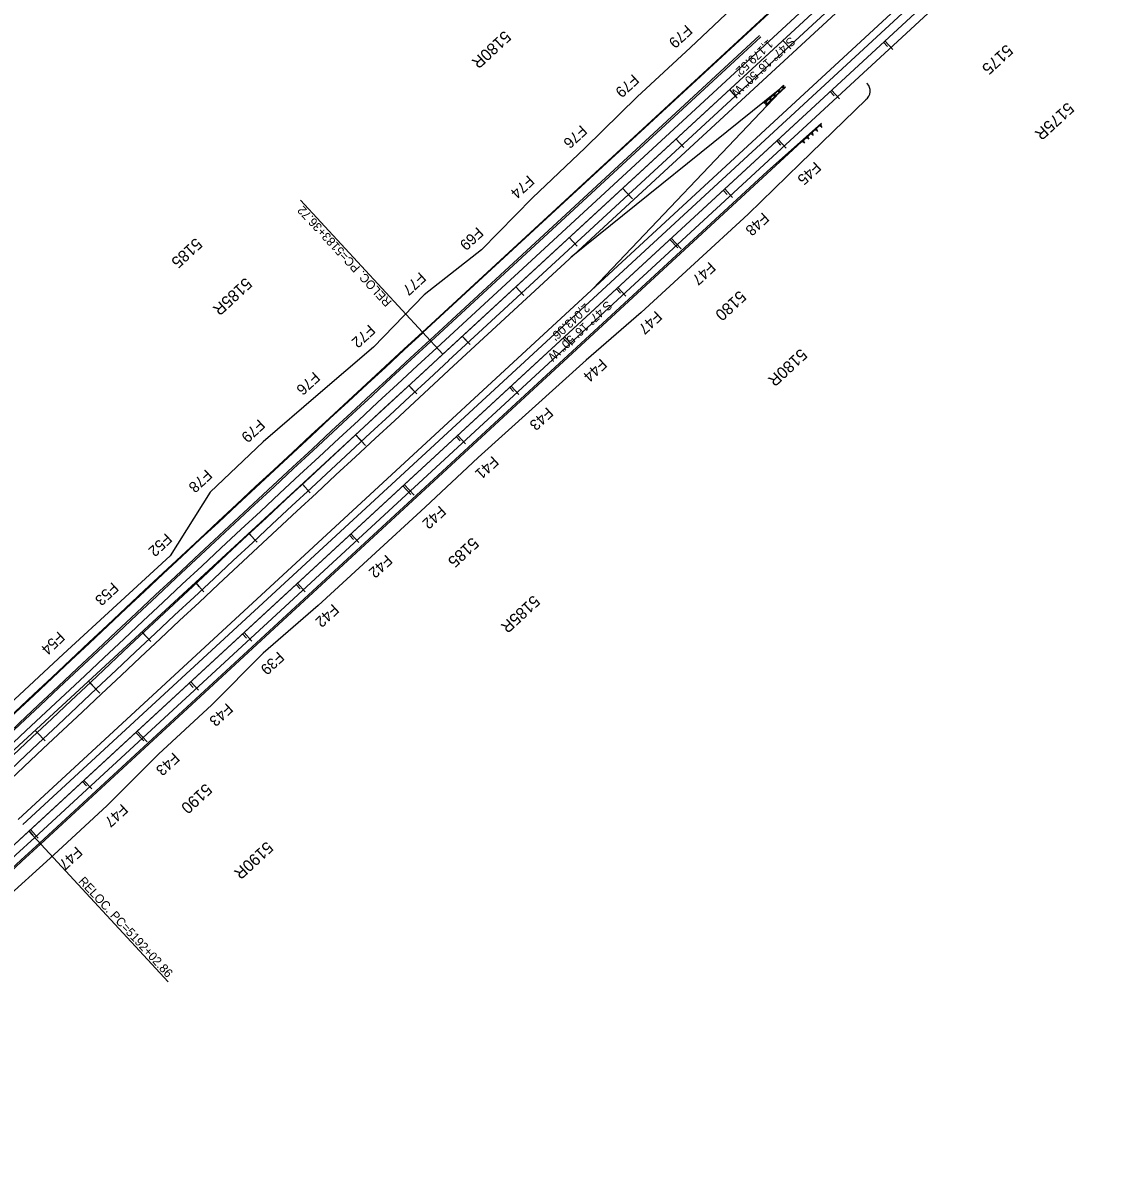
# Model space of a CAD drawing. Extents: x 2160877 to 2175861, y 601747 to 617724.
# Drawn here: x 2170763 to 2172272, y 611849 to 613431 of the extents above; entities that cross this region are included whole.
import ezdxf

# ---------------------------------------------------------------- set-up
doc = ezdxf.new("R2010")
doc.units = 0
for name, color, linetype in [('RD_HC_Cl', 7, 'Continuous'), ('RD_HC_CL_Rel', 7, 'Continuous'), ('RD_HC_Data_Rel', 7, 'Continuous'), ('RD_HC_Data_Tic', 7, 'Continuous'), ('RD_HC_Data_Tic_Rel', 7, 'Continuous'), ('RD_HC_TX_Rel_Sta50', 7, 'Continuous'), ('RD_HC_TX_Rel_StaOther', 7, 'Continuous'), ('RD_HC_TX_StaOther', 7, 'Continuous'), ('RD_PD_CstnLmt', 7, 'Continuous'), ('RD_PD_CstnLmt_TX', 7, 'Continuous'), ('RD_PD_Final_LnLine', 7, 'Continuous'), ('RD_PD_Final_TrvlWay', 7, 'Continuous'), ('RD_PD_GR', 7, 'Continuous'), ('RD_PD_MedBWall', 7, 'Continuous')]:
    doc.layers.add(name, color=color, linetype=linetype)

msp = doc.modelspace()

# ---------------------------------------------------------------- linework, layer by layer
at = {"layer": 'RD_HC_Cl'}
for p, q in [((2172207.3, 613775.1), (2163672.2, 605893.8)), ((2172272.5, 613704.6), (2163737.4, 605823.3))]:
    msp.add_line(p, q, dxfattribs=at)
at = {"layer": 'RD_HC_CL_Rel'}
for p, q in [((2172207.3, 613775.1), (2171340.7, 612974.9)), ((2172272.5, 613704.6), (2170771.4, 612318.6))]:
    msp.add_line(p, q, dxfattribs=at)
for centre, radius in [((2222221.5, 557873.6), 75000), ((2219616.9, 559421.3), 72000)]:
    msp.add_arc(centre, radius, 132.719474, 134.517591, dxfattribs=at)
at = {"layer": 'RD_HC_Data_Rel'}
for p, q in [((2171340.7, 612974.9), (2171145.2, 613186.7)), ((2170771.4, 612318.6), (2170963.2, 612110.9))]:
    msp.add_line(p, q, dxfattribs=at)
at = {"layer": 'RD_HC_Data_Tic'}
for p, q in [((2171808.5, 613406.9), (2171814, 613401)), ((2171947.1, 613404.2), (2171952.6, 613398.3)), ((2171735.1, 613339.1), (2171740.5, 613333.2)), ((2171873.7, 613336.4), (2171879.1, 613330.5)), ((2171661.6, 613271.2), (2171667, 613265.3)), ((2171800.2, 613268.5), (2171805.6, 613262.7)), ((2171588.1, 613203.4), (2171599, 613191.6)), ((2171726.7, 613200.7), (2171732.2, 613194.8)), ((2171514.7, 613135.5), (2171520.1, 613129.7)), ((2171653.3, 613132.8), (2171664.1, 613121.1)), ((2171441.2, 613067.7), (2171446.6, 613061.8)), ((2171579.8, 613065), (2171585.2, 613059.1)), ((2171367.7, 612999.9), (2171373.2, 612994)), ((2171506.3, 612997.2), (2171511.8, 612991.3)), ((2171294.3, 612932), (2171299.7, 612926.1)), ((2171432.9, 612929.3), (2171438.3, 612923.4)), ((2171220.8, 612864.2), (2171231.6, 612852.4)), ((2171359.4, 612861.5), (2171364.8, 612855.6)), ((2171147.3, 612796.3), (2171152.7, 612790.5)), ((2171285.9, 612793.6), (2171296.8, 612781.9)), ((2171073.9, 612728.5), (2171079.3, 612722.6)), ((2171212.4, 612725.8), (2171217.9, 612719.9)), ((2171000.4, 612660.7), (2171005.8, 612654.8)), ((2171139, 612658), (2171144.4, 612652.1)), ((2170926.9, 612592.8), (2170932.3, 612586.9)), ((2171065.5, 612590.1), (2171070.9, 612584.2)), ((2170853.4, 612525), (2170864.3, 612513.2)), ((2170992, 612522.3), (2170997.5, 612516.4)), ((2170780, 612457.1), (2170785.4, 612451.3)), ((2170918.6, 612454.4), (2170929.4, 612442.7)), ((2170845.1, 612386.6), (2170850.5, 612380.7)), ((2170771.6, 612318.8), (2170777.1, 612312.9))]:
    msp.add_line(p, q, dxfattribs=at)
at = {"layer": 'RD_HC_Data_Tic_Rel'}
for p, q in [((2171808.5, 613406.9), (2171819.4, 613395.1)), ((2171949, 613406), (2171959.9, 613394.2)), ((2171735.1, 613339.1), (2171745.9, 613327.3)), ((2171875.6, 613338.1), (2171886.4, 613326.4)), ((2171661.6, 613271.2), (2171672.5, 613259.5)), ((2171802.1, 613270.3), (2171813, 613258.5)), ((2171588.1, 613203.4), (2171601.7, 613188.7)), ((2171728.6, 613202.5), (2171739.5, 613190.7)), ((2171514.7, 613135.5), (2171525.5, 613123.8)), ((2171655.2, 613134.6), (2171668.7, 613119.9)), ((2171441.2, 613067.7), (2171452.1, 613055.9)), ((2171581.7, 613066.8), (2171592.6, 613055)), ((2171367.7, 612999.9), (2171378.6, 612988.1)), ((2171508.2, 612998.9), (2171519.1, 612987.2)), ((2171294.3, 612932), (2171305.1, 612920.2)), ((2171434.8, 612931.1), (2171445.6, 612919.3)), ((2171220.9, 612864), (2171234.5, 612849.4)), ((2171361.3, 612863.2), (2171372.2, 612851.5)), ((2171147.6, 612796), (2171158.5, 612784.3)), ((2171287.8, 612795.4), (2171301.4, 612780.7)), ((2171074.5, 612727.8), (2171085.4, 612716.1)), ((2171214.4, 612727.6), (2171225.2, 612715.8)), ((2171001.4, 612659.6), (2171012.3, 612647.9)), ((2171140.9, 612659.7), (2171151.7, 612648)), ((2170928.4, 612591.3), (2170939.3, 612579.6)), ((2171067.4, 612591.9), (2171078.3, 612580.1)), ((2170855.4, 612522.8), (2170869.1, 612508.2)), ((2170994, 612524), (2171004.8, 612512.3)), ((2170782.6, 612454.3), (2170793.6, 612442.6)), ((2170920.5, 612456.2), (2170934.1, 612441.5)), ((2170847, 612388.4), (2170857.9, 612376.6)), ((2170773.5, 612320.5), (2170784.4, 612308.8))]:
    msp.add_line(p, q, dxfattribs=at)
at = {"layer": 'RD_PD_CstnLmt'}
for p, q in [((2171754.2, 613465.7), (2171681.6, 613397)), ((2171681.6, 613397), (2171608.1, 613329.1)), ((2171924.2, 613348.1), (2171924.8, 613347.4)), ((2171608.1, 613329.1), (2171536.7, 613259)), ((2171922.9, 613325.2), (2171832.4, 613237.5)), ((2171536.7, 613259), (2171464.3, 613190.1)), ((2171832.4, 613237.5), (2171760.9, 613167.5)), ((2171464.3, 613190.1), (2171394.1, 613118.7)), ((2171760.9, 613167.5), (2171687.3, 613099.8)), ((2171394.1, 613118.7), (2171315.2, 613056.8)), ((2171687.3, 613099.8), (2171613.7, 613032.1)), ((2171315.2, 613056.8), (2171245.5, 612984.7)), ((2171613.7, 613032.1), (2171538.1, 612966.6)), ((2171245.5, 612984.7), (2171169.4, 612919.6)), ((2171538.1, 612966.6), (2171463.8, 612899.6)), ((2171169.4, 612919.6), (2171093.5, 612854.2)), ((2171463.8, 612899.6), (2171389.4, 612832.8)), ((2171093.5, 612854.2), (2171021, 612785.2)), ((2171389.4, 612832.8), (2171316.6, 612764.2)), ((2171021, 612785.2), (2170966, 612697.4)), ((2171316.6, 612764.2), (2171242.9, 612696.6)), ((2170966, 612697.4), (2170892.2, 612629.8)), ((2171242.9, 612696.6), (2171169.4, 612628.9)), ((2170892.2, 612629.8), (2170818.5, 612562.2)), ((2171169.4, 612628.9), (2171093.9, 612563.2)), ((2170818.5, 612562.2), (2170745.3, 612493.8)), ((2171093.9, 612563.2), (2171023.3, 612492.3)), ((2171023.3, 612492.3), (2170949.9, 612424.4)), ((2170949.9, 612424.4), (2170879, 612353.7)), ((2170879, 612353.7), (2170805.7, 612285.7)), ((2170805.7, 612285.7), (2170731.3, 612218.9))]:
    msp.add_line(p, q, dxfattribs=at)
msp.add_arc((2171913.8, 613337.2), 15, 307.2254, 42.7195, dxfattribs=at)
at = {"layer": 'RD_PD_Final_LnLine'}
for p, q in [((2172199.2, 613784), (2171332.6, 612983.8)), ((2172215.5, 613766.3), (2171348.9, 612966.1)), ((2172264.3, 613713.4), (2170763.3, 612327.4)), ((2172224.1, 613643.7), (2170779.6, 612309.8)), ((2171802, 613337.9), (2171517.6, 613108.3)), ((2171804.3, 613335.4), (2171547.4, 613065))]:
    msp.add_line(p, q, dxfattribs=at)
for centre, radius in [((2222221.5, 557873.6), 75012), ((2222221.5, 557873.6), 74988), ((2219616.9, 559421.3), 71988)]:
    msp.add_arc(centre, radius, 132.719474, 134.517591, dxfattribs=at)
at = {"layer": 'RD_PD_Final_TrvlWay'}
for p, q in [((2172222.2, 613759), (2171355.7, 612958.8)), ((2172257.5, 613720.8), (2170756.5, 612334.7)), ((2171776.7, 613413.4), (2171322.9, 612994.3)), ((2171778.3, 613411.6), (2171324.5, 612992.6)), ((2171787.2, 613226.6), (2171862, 613293)), ((2171787.2, 613226.6), (2170786.4, 612302.4))]:
    msp.add_line(p, q, dxfattribs=at)
for centre, radius in [((2222220.1, 557875.1), 75024.3), ((2222220.1, 557875.1), 75022), ((2222221.5, 557873.6), 74978), ((2219616.9, 559421.3), 71978)]:
    msp.add_arc(centre, radius, 132.719474, 134.517591, dxfattribs=at)
at = {"layer": 'RD_PD_GR'}
for p, q in [((2171809.9, 613345.3), (2171782.7, 613320.2)), ((2171783, 613319.8), (2171810.2, 613344.9)), ((2171784.9, 613317.9), (2171812, 613343)), ((2171812.4, 613342.6), (2171785.2, 613317.5)), ((2171801.4, 613337.6), (2171802.6, 613338.7)), ((2171801.8, 613337.1), (2171803, 613338.3)), ((2171803.1, 613335.7), (2171801.8, 613337.1)), ((2171802.9, 613337.2), (2171802, 613338.1)), ((2171803.5, 613337.8), (2171802.2, 613336.6)), ((2171802.2, 613336.6), (2171803.6, 613335.2)), ((2171803, 613338.3), (2171804.4, 613336.8)), ((2171804.4, 613336.8), (2171803.1, 613335.7)), ((2171804.9, 613336.4), (2171803.5, 613337.8)), ((2171803.6, 613335.2), (2171804.9, 613336.4)), ((2171803.8, 613336.2), (2171804.6, 613335.3)), ((2171807.2, 613343), (2171808.5, 613344.2)), ((2171807.6, 613342.6), (2171808.9, 613343.7)), ((2171809, 613341.1), (2171807.6, 613342.6)), ((2171808.7, 613342.7), (2171807.9, 613343.6)), ((2171809.4, 613343.2), (2171808.1, 613342.1)), ((2171808.1, 613342.1), (2171809.4, 613340.6)), ((2171808.9, 613343.7), (2171810.3, 613342.3)), ((2171810.3, 613342.3), (2171809, 613341.1)), ((2171810.7, 613341.8), (2171809.4, 613343.2)), ((2171809.4, 613340.6), (2171810.7, 613341.8)), ((2171809.6, 613341.7), (2171810.5, 613340.8)), ((2171809.8, 613340.2), (2171811.1, 613341.3)), ((2171810.2, 613344.9), (2171809.9, 613345.3)), ((2171812, 613343), (2171812.4, 613342.6)), ((2171783.7, 613321.3), (2171785, 613322.5)), ((2171784.1, 613320.8), (2171785.4, 613322)), ((2171785.5, 613319.4), (2171784.1, 613320.8)), ((2171785.2, 613320.9), (2171784.4, 613321.9)), ((2171785.9, 613321.5), (2171784.6, 613320.4)), ((2171785.4, 613322), (2171786.8, 613320.6)), ((2171786.8, 613320.6), (2171785.5, 613319.4)), ((2171787.2, 613320.1), (2171785.9, 613321.5)), ((2171787.7, 613324.1), (2171787.4, 613324.5)), ((2171789.5, 613322.2), (2171789.9, 613321.8)), ((2171789.6, 613326.7), (2171790.9, 613327.9)), ((2171790, 613326.3), (2171791.3, 613327.5)), ((2171791.4, 613324.8), (2171790, 613326.3)), ((2171791.1, 613326.4), (2171790.3, 613327.3)), ((2171791.7, 613327), (2171790.5, 613325.8)), ((2171790.5, 613325.8), (2171791.8, 613324.3)), ((2171791.3, 613327.5), (2171792.6, 613326)), ((2171792.6, 613326), (2171791.4, 613324.8)), ((2171793.1, 613325.5), (2171791.7, 613327)), ((2171791.8, 613324.3), (2171793.1, 613325.5)), ((2171792, 613325.4), (2171792.9, 613324.5)), ((2171792.2, 613323.9), (2171793.5, 613325.1)), ((2171795.5, 613332.1), (2171796.8, 613333.3)), ((2171795.9, 613331.7), (2171797.2, 613332.9)), ((2171797.2, 613330.2), (2171795.9, 613331.7)), ((2171797, 613331.8), (2171796.1, 613332.7)), ((2171797.6, 613332.4), (2171796.3, 613331.2)), ((2171796.3, 613331.2), (2171797.7, 613329.7)), ((2171797.2, 613332.9), (2171798.5, 613331.4)), ((2171798.5, 613331.4), (2171797.2, 613330.2)), ((2171799, 613330.9), (2171797.6, 613332.4)), ((2171797.7, 613329.7), (2171799, 613330.9)), ((2171797.9, 613330.8), (2171798.7, 613329.9)), ((2171798.1, 613329.3), (2171799.4, 613330.5)), ((2171804, 613334.7), (2171805.3, 613335.9)), ((2171782.7, 613320.2), (2171783, 613319.8)), ((2171784.6, 613320.4), (2171785.9, 613318.9)), ((2171785.2, 613317.5), (2171784.9, 613317.9)), ((2171785.9, 613318.9), (2171787.2, 613320.1)), ((2171786.1, 613320), (2171787, 613319)), ((2171786.3, 613318.5), (2171787.6, 613319.6)), ((2171861.2, 613292.3), (2171834.1, 613267.2)), ((2171834.4, 613266.9), (2171861.6, 613292)), ((2171859, 613289.6), (2171860.3, 613290.8)), ((2171860.3, 613288.1), (2171859, 613289.6)), ((2171860.3, 613290.8), (2171861.6, 613289.3)), ((2171861.6, 613289.3), (2171860.3, 613288.1)), ((2171861.6, 613292), (2171861.2, 613292.3)), ((2171841.4, 613273.3), (2171842.6, 613274.5)), ((2171842.7, 613271.8), (2171841.4, 613273.3)), ((2171842.6, 613274.5), (2171844, 613273)), ((2171844, 613273), (2171842.7, 613271.8)), ((2171847.2, 613278.7), (2171848.5, 613279.9)), ((2171848.6, 613277.3), (2171847.2, 613278.7)), ((2171848.5, 613279.9), (2171849.9, 613278.4)), ((2171849.9, 613278.4), (2171848.6, 613277.3)), ((2171849.2, 613277.8), (2171850.1, 613276.9)), ((2171849.4, 613276.3), (2171850.7, 613277.5)), ((2171853.1, 613284.2), (2171854.4, 613285.3)), ((2171854.5, 613282.7), (2171853.1, 613284.2)), ((2171854.4, 613285.3), (2171855.7, 613283.9)), ((2171855.7, 613283.9), (2171854.5, 613282.7)), ((2171855.1, 613283.3), (2171856, 613282.4)), ((2171855.3, 613281.8), (2171856.6, 613283)), ((2171861, 613288.7), (2171861.8, 613287.8)), ((2171861.2, 613287.2), (2171862.5, 613288.4)), ((2170787.7, 612300.9), (2171834.1, 613267.2)), ((2171834.1, 613267.2), (2171834.4, 613266.9)), ((2171835.5, 613267.9), (2171836.8, 613269.1)), ((2171836.8, 613266.4), (2171835.5, 613267.9)), ((2171836.8, 613269.1), (2171838.1, 613267.6)), ((2171838.1, 613267.6), (2171836.8, 613266.4)), ((2171837.5, 613267), (2171838.3, 613266.1)), ((2171837.7, 613265.5), (2171839, 613266.7)), ((2171839.1, 613271.2), (2171838.7, 613271.5)), ((2171843.4, 613272.4), (2171844.2, 613271.5)), ((2171843.6, 613270.9), (2171844.8, 613272.1))]:
    msp.add_line(p, q, dxfattribs=at)
msp.add_arc((2219616.9, 559421.3), 71976, 132.719474, 134.517591, dxfattribs=at)
at = {"layer": 'RD_PD_MedBWall'}
for p, q in [((2172075.1, 613709.3), (2171312.7, 613005.3)), ((2172075.8, 613708.6), (2171313.4, 613004.6))]:
    msp.add_line(p, q, dxfattribs=at)
for radius, end in [(75039.3, 134.421287), (75038.3, 134.421298)]:
    msp.add_arc((2222220.1, 557875.1), radius, 132.719474, end, dxfattribs=at)

# ---------------------------------------------------------------- texts
at = {"layer": 'RD_HC_Data_Rel'}
for s, rotation, p in [('RELOC. PC=5183+36.72', 132.7195, (2171271.4, 613047.1)), ('RELOC. PC=5192+02.86', 312.7195, (2170838.9, 612248.9))]:
    msp.add_text(s, height=12, rotation=rotation, dxfattribs=at).set_placement(p)
at = {"layer": 'RD_HC_TX_Rel_Sta50'}
for s, rotation, p in [('5180R', 222.7195, (2171425.6, 613421.1)), ('5175R', 222.7195, (2172200.2, 613322.6)), ('5185R', 222.8442, (2171069.3, 613081.3)), ('5180R', 222.7195, (2171833.1, 612983.6)), ('5185R', 222.7195, (2171465.5, 612644.2)), ('5190R', 222.7195, (2171098.4, 612305.2))]:
    msp.add_text(s, height=16, rotation=rotation, dxfattribs=at).set_placement(p)
at = {"layer": 'RD_HC_TX_Rel_StaOther'}
for s, p in [('S 47%%d 16\' 50" W', (2171819.1, 613412.6)), ("1,179.52'", (2171788.7, 613409)), ('S 47%%d 16\' 50" W', (2171567, 613049.2)), ("2,043.06'", (2171536.6, 613045.6))]:
    msp.add_text(s, height=12, rotation=222.7195, dxfattribs=at).set_placement(p)
at = {"layer": 'RD_HC_TX_StaOther'}
for s, p in [('5175', (2172116.1, 613402.3)), ('5185', (2171000.9, 613136)), ('5180', (2171749.1, 613063.5)), ('5185', (2171381.4, 612723.9)), ('5190', (2171014.4, 612385))]:
    msp.add_text(s, height=16, rotation=222.7195, dxfattribs=at).set_placement(p)
at = {"layer": 'RD_PD_CstnLmt_TX'}
for s, rotation, p in [('F79', 222.7195, (2171675.7, 613429.2)), ('F79', 222.7195, (2171602.3, 613361.3)), ('F76', 222.7195, (2171530.8, 613291.2)), ('F45', 222.7195, (2171852.7, 613240.9)), ('F74', 222.7195, (2171458.2, 613222.1)), ('F48', 222.7195, (2171781.2, 613170.9)), ('F69', 222.7195, (2171388.2, 613150.9)), ('F47', 222.7195, (2171707.6, 613103.1)), ('F77', 222.7195, (2171309.2, 613088.9)), ('F47', 222.7195, (2171633.9, 613035.5)), ('F72', 222.7678, (2171239.4, 613016.7)), ('F44', 222.7195, (2171558.2, 612969.8)), ('F76', 222.8442, (2171163.4, 612951.7)), ('F43', 222.7195, (2171484.2, 612903)), ('F79', 222.9206, (2171087.6, 612886.4)), ('F41', 222.7195, (2171409.2, 612835.8)), ('F78', 222.997, (2171015, 612817.4)), ('F42', 222.7195, (2171336.7, 612767.4)), ('F52', 223.0734, (2170959.8, 612729.5)), ('F42', 222.7195, (2171263, 612699.9)), ('F53', 223.1498, (2170886.2, 612662)), ('F42', 222.7195, (2171189.5, 612632.1)), ('F54', 223.2262, (2170812.2, 612594.2)), ('F39', 222.7195, (2171114.2, 612566.6)), ('F43', 222.7195, (2171043.6, 612495.7)), ('F43', 222.7195, (2170970.2, 612427.8)), ('F47', 222.7195, (2170899.2, 612357.1)), ('F47', 222.7195, (2170836.6, 612298.4))]:
    msp.add_text(s, height=15, rotation=rotation, dxfattribs=at).set_placement(p)

doc.saveas('drawing.dxf')
